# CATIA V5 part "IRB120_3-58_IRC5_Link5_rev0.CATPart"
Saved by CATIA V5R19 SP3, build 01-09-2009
Part number: IRB120_3-58_IRC5_Link5_rev0
Revision: ANY
Definition: UNKNOWN
Nomenclature: IRB120_3-58_IRC5_Link5_rev0
Source: Unknown
Bounding box of the stored display mesh (mm): x 236 to 368, y -35 to 35, z 589 to 671
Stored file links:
  Z:\Projects\ABB_Robotics\ABB LIB\V5\V5PARTS\ABB\120\IRB120_3-58_IRC5_Link5_rev0.CATPart
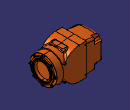
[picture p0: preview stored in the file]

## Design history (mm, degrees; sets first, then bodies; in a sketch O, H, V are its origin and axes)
Set1
  DatumSurface1 "NONE"
Body1 "NONE" (main body)
  Solid1: solid without history
Body2 "NONE"
  Solid2: solid without history
Body3 "NONE"
  Solid3: solid without history
Body4 "NONE"
  Solid4: solid without history
  Fill1: Boundary (edge of DatumSurface1; edge of DatumSurface1; edge of DatumSurface1; edge of DatumSurface1; edge of DatumSurface1; edge of DatumSurface1)
  Fill2: Boundary (edge of DatumSurface1; edge of DatumSurface1; edge of DatumSurface1; edge of DatumSurface1; edge of DatumSurface1; edge of DatumSurface1)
